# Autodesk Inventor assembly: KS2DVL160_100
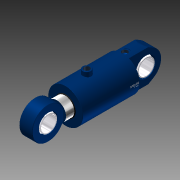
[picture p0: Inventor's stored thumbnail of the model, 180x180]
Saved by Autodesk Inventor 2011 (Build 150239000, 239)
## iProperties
Created: 2010-11
Document SubType Name: Assembly
Designer: TB
Mass: 566.294 g
Surface Area: 1153.75 cm^2
Volume: 566.294 cm^3
Density: 1 g/cm^3
Description: KS2DVL 160/100 - 100 mm
Slaglengde: 100,000 mm
Author: TB
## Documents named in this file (6)
- C:\Vault\Sylinderteknikk\Projects_ST\3D.nettkatalog\KS2-Series\KS2DVL\KS2DVL160_100\KS2DVL160_100.iam
- C:\Vault\Sylinderteknikk\Projects_ST\3D.nettkatalog\KS2-Series\KS2DVL\KS2DVL160_100\KS2DVL160_100_stang.ipt
- C:\Vault\Sylinderteknikk\Projects_ST\3D.nettkatalog\KS2-Series\KS2DVL\KS2DVL160_100\KS2DVL160_100_Parameters.ipt
- C:\Vault\Sylinderteknikk\Projects_ST\3D.nettkatalog\KS2-Series\KS2DVL\KS2DVL160_100\KS2DVL160_100_body..ipt
- C:\Vault\Sylinderteknikk\Projects_ST\Øyer\Klinkby.KS.Øyer\KS.80.eye.komplett\Kule80HO.ipt
- C:\Vault\Sylinderteknikk\Projects_ST\Øyer\Klinkby.KS.Øyer\KS.80.eye.komplett\KS.80.eye.komplett.1.ipt
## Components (5 placed, 5 different names)
1. KS2DVL160_100_Parameters:3
2. KS2DVL160_100_stang:1 — Mate:1, FriMate:2, Mate:3, Insert:3
3. KS2DVL160_100_body.:1 — Mate:1, FriMate:2, Mate:3, Insert:2, Angle:1
4. Kule80HO:1 — Insert:2
5. KS.80.eye.komplett.1:1 — Insert:3, Angle:1
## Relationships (6: Mate 3, Insert 2, Angle 1)
- Mate:1: KS2DVL160_100_stang:1 ↔ KS2DVL160_100_body.:1
- FriMate:2 [Mate]: KS2DVL160_100_stang:1 ↔ KS2DVL160_100_body.:1
- Mate:3: KS2DVL160_100_stang:1 ↔ KS2DVL160_100_body.:1
- Insert:2: KS2DVL160_100_body.:1 ↔ Kule80HO:1
- Insert:3: KS2DVL160_100_stang:1 ↔ KS.80.eye.komplett.1:1
- Angle:1: KS2DVL160_100_body.:1 ↔ KS.80.eye.komplett.1:1
## Named parameters: Forlengelse_rør = 0, Vinkel_Minusport = 0
